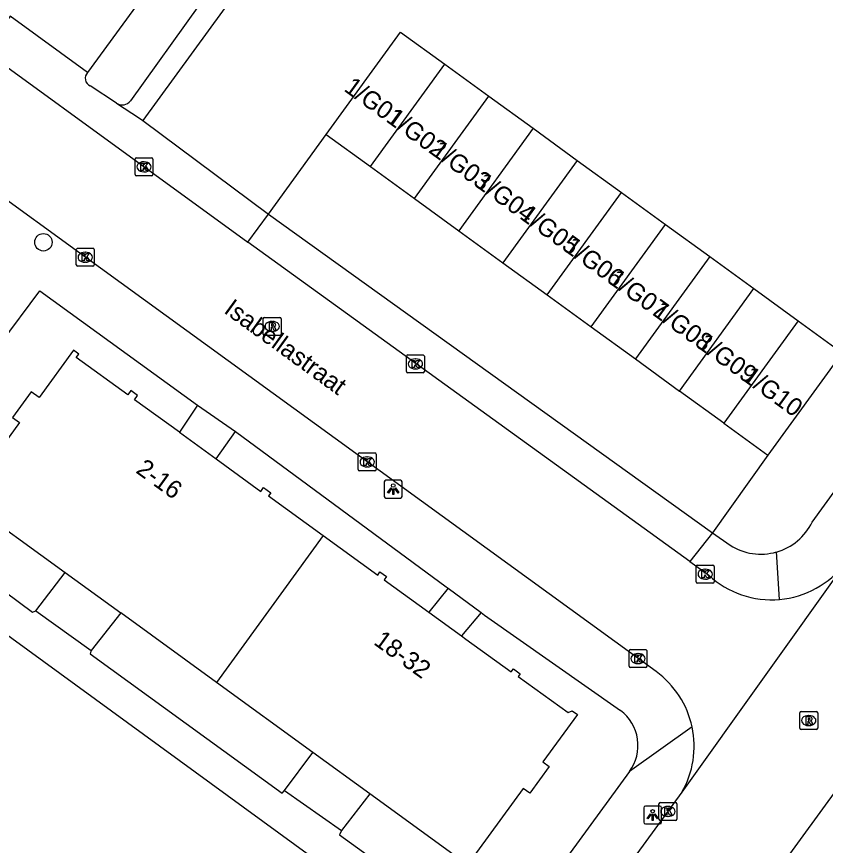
# Model space of a CAD drawing. Extents: x 160107 to 160928, y 382056 to 382918.
# Drawn here: x 160345.01 to 160390.23, y 382406.18 to 382452.51 of the extents above; entities that cross this region are included whole.
import ezdxf

# ---------------------------------------------------------------- set-up
doc = ezdxf.new("R2010")
doc.units = 0
for name, color, linetype in [('IMGEO_Boom', 7, 'Continuous'), ('IMGEO_Kolk', 7, 'Continuous'), ('IMGEO_Lichtpunt', 7, 'Continuous'), ('IMGEO_Openbare_ruimte_label', 7, 'Continuous'), ('IMGEO_Pand', 7, 'Continuous'), ('IMGEO_Pand_nummerreeks', 7, 'Continuous'), ('IMGEO_Parkeervlak_open', 7, 'Continuous'), ('IMGEO_Rijbaan_lokaal_open', 7, 'Continuous'), ('IMGEO_Rioolput', 7, 'Continuous'), ('IMGEO_Voetpad_gesloten', 7, 'Continuous'), ('IMGEO_Voetpad_op_trap', 7, 'Continuous'), ('IMGEO_Voetpad_open', 7, 'Continuous')]:
    doc.layers.add(name, color=color, linetype=linetype)

msp = doc.modelspace()

# ---------------------------------------------------------------- linework, layer by layer
at = {"layer": 'IMGEO_Boom'}
msp.add_circle((160346.516, 382439.892), 0.489, dxfattribs=at)
at = {"layer": 'IMGEO_Kolk'}
for p, q in [((160351.639, 382443.681), (160351.639, 382444.533)), ((160351.714, 382444.607), (160352.566, 382444.607)), ((160352.127, 382444.387), (160352.152, 382444.387)), ((160352.64, 382444.533), (160352.64, 382443.681)), ((160352.566, 382443.607), (160351.714, 382443.607)), ((160352.15, 382443.827), (160352.125, 382443.827)), ((160348.352, 382438.629), (160348.352, 382439.481)), ((160348.427, 382439.555), (160349.279, 382439.555)), ((160348.84, 382439.335), (160348.865, 382439.335)), ((160349.353, 382439.481), (160349.353, 382438.629)), ((160348.863, 382438.775), (160348.838, 382438.775)), ((160349.279, 382438.555), (160348.427, 382438.555)), ((160366.812, 382432.666), (160366.812, 382433.518)), ((160366.887, 382433.592), (160367.739, 382433.592)), ((160367.3, 382433.372), (160367.325, 382433.372)), ((160367.813, 382433.518), (160367.813, 382432.666)), ((160367.323, 382432.812), (160367.298, 382432.812)), ((160367.739, 382432.592), (160366.887, 382432.592)), ((160364.191, 382428.114), (160365.043, 382428.114)), ((160364.116, 382427.188), (160364.116, 382428.04)), ((160364.604, 382427.894), (160364.629, 382427.894)), ((160365.117, 382428.04), (160365.117, 382427.188)), ((160364.627, 382427.334), (160364.602, 382427.334)), ((160365.043, 382427.114), (160364.191, 382427.114)), ((160383.011, 382420.915), (160383.011, 382421.767)), ((160383.086, 382421.841), (160383.938, 382421.841)), ((160383.499, 382421.621), (160383.524, 382421.621)), ((160384.012, 382421.767), (160384.012, 382420.915)), ((160383.938, 382420.841), (160383.086, 382420.841)), ((160383.522, 382421.061), (160383.497, 382421.061)), ((160379.257, 382416.199), (160379.257, 382417.051)), ((160379.332, 382417.125), (160380.184, 382417.125)), ((160380.258, 382417.051), (160380.258, 382416.199)), ((160379.745, 382416.905), (160379.77, 382416.905)), ((160380.184, 382416.125), (160379.332, 382416.125)), ((160379.768, 382416.345), (160379.743, 382416.345)), ((160380.926, 382407.653), (160380.926, 382408.505)), ((160381.001, 382408.579), (160381.853, 382408.579)), ((160381.414, 382408.359), (160381.439, 382408.359)), ((160381.927, 382408.505), (160381.927, 382407.653)), ((160381.437, 382407.799), (160381.412, 382407.799)), ((160381.853, 382407.579), (160381.001, 382407.579))]:
    msp.add_line(p, q, dxfattribs=at)
for points in [[(160351.639, 382443.681), (160351.639, 382444.533)], [(160351.714, 382444.607), (160352.566, 382444.607)], [(160352.64, 382444.533), (160352.64, 382443.681)], [(160351.96, 382444.307), (160352.083, 382444.307), (160352.083, 382444.156), (160352.213, 382444.307), (160352.377, 382444.307), (160352.231, 382444.156), (160352.384, 382443.907), (160352.232, 382443.907), (160352.147, 382444.071), (160352.083, 382444.004), (160352.083, 382443.907), (160351.96, 382443.907), (160351.96, 382444.307)], [(160352.566, 382443.607), (160351.714, 382443.607)], [(160348.352, 382438.629), (160348.352, 382439.481)], [(160348.427, 382439.555), (160349.279, 382439.555)], [(160348.673, 382439.255), (160348.796, 382439.255), (160348.796, 382439.104), (160348.926, 382439.255), (160349.09, 382439.255), (160348.944, 382439.104), (160349.097, 382438.855), (160348.945, 382438.855), (160348.86, 382439.019), (160348.796, 382438.952), (160348.796, 382438.855), (160348.673, 382438.855), (160348.673, 382439.255)], [(160349.353, 382439.481), (160349.353, 382438.629)], [(160349.279, 382438.555), (160348.427, 382438.555)], [(160366.812, 382432.666), (160366.812, 382433.518)], [(160366.887, 382433.592), (160367.739, 382433.592)], [(160367.133, 382433.292), (160367.256, 382433.292), (160367.256, 382433.141), (160367.386, 382433.292), (160367.55, 382433.292), (160367.404, 382433.141), (160367.557, 382432.892), (160367.405, 382432.892), (160367.32, 382433.056), (160367.256, 382432.989), (160367.256, 382432.892), (160367.133, 382432.892), (160367.133, 382433.292)], [(160367.813, 382433.518), (160367.813, 382432.666)], [(160367.739, 382432.592), (160366.887, 382432.592)], [(160364.191, 382428.114), (160365.043, 382428.114)], [(160364.116, 382427.188), (160364.116, 382428.04)], [(160364.437, 382427.814), (160364.56, 382427.814), (160364.56, 382427.663), (160364.69, 382427.814), (160364.854, 382427.814), (160364.708, 382427.663), (160364.861, 382427.414), (160364.709, 382427.414), (160364.624, 382427.578), (160364.56, 382427.511), (160364.56, 382427.414), (160364.437, 382427.414), (160364.437, 382427.814)], [(160365.117, 382428.04), (160365.117, 382427.188)], [(160365.043, 382427.114), (160364.191, 382427.114)], [(160383.011, 382420.915), (160383.011, 382421.767)], [(160383.086, 382421.841), (160383.938, 382421.841)], [(160384.012, 382421.767), (160384.012, 382420.915)], [(160383.332, 382421.541), (160383.455, 382421.541), (160383.455, 382421.39), (160383.585, 382421.541), (160383.749, 382421.541), (160383.603, 382421.39), (160383.756, 382421.141), (160383.604, 382421.141), (160383.519, 382421.305), (160383.455, 382421.238), (160383.455, 382421.141), (160383.332, 382421.141), (160383.332, 382421.541)], [(160383.938, 382420.841), (160383.086, 382420.841)], [(160379.257, 382416.199), (160379.257, 382417.051)], [(160379.332, 382417.125), (160380.184, 382417.125)], [(160380.258, 382417.051), (160380.258, 382416.199)], [(160379.578, 382416.825), (160379.701, 382416.825), (160379.701, 382416.674), (160379.831, 382416.825), (160379.995, 382416.825), (160379.849, 382416.674), (160380.002, 382416.425), (160379.85, 382416.425), (160379.765, 382416.589), (160379.701, 382416.522), (160379.701, 382416.425), (160379.578, 382416.425), (160379.578, 382416.825)], [(160380.184, 382416.125), (160379.332, 382416.125)], [(160380.926, 382407.653), (160380.926, 382408.505)], [(160381.001, 382408.579), (160381.853, 382408.579)], [(160381.247, 382408.279), (160381.37, 382408.279), (160381.37, 382408.128), (160381.5, 382408.279), (160381.664, 382408.279), (160381.518, 382408.128), (160381.671, 382407.879), (160381.519, 382407.879), (160381.434, 382408.043), (160381.37, 382407.976), (160381.37, 382407.879), (160381.247, 382407.879), (160381.247, 382408.279)], [(160381.927, 382408.505), (160381.927, 382407.653)], [(160381.853, 382407.579), (160381.001, 382407.579)]]:
    msp.add_lwpolyline(points, dxfattribs=at)
for centre, start, end in [((160351.716, 382444.531), 91.552, 178.448), ((160351.716, 382444.531), 91.552, 178.448), ((160352.564, 382444.531), 1.552, 88.448), ((160352.564, 382444.531), 1.552, 88.448), ((160351.716, 382443.683), 181.552, 268.448), ((160351.716, 382443.683), 181.552, 268.448), ((160352.564, 382443.683), 271.552, 358.448), ((160352.564, 382443.683), 271.552, 358.448), ((160348.429, 382439.479), 91.552, 178.448), ((160348.429, 382439.479), 91.552, 178.448), ((160349.277, 382439.479), 1.552, 88.448), ((160349.277, 382439.479), 1.552, 88.448), ((160348.429, 382438.631), 181.552, 268.448), ((160348.429, 382438.631), 181.552, 268.448), ((160349.277, 382438.631), 271.552, 358.448), ((160349.277, 382438.631), 271.552, 358.448), ((160366.889, 382433.516), 91.552, 178.448), ((160366.889, 382433.516), 91.552, 178.448), ((160367.737, 382433.516), 1.552, 88.448), ((160367.737, 382433.516), 1.552, 88.448), ((160366.889, 382432.668), 181.552, 268.448), ((160366.889, 382432.668), 181.552, 268.448), ((160367.737, 382432.668), 271.552, 358.448), ((160367.737, 382432.668), 271.552, 358.448), ((160364.193, 382428.038), 91.552, 178.448), ((160364.193, 382428.038), 91.552, 178.448), ((160365.041, 382428.038), 1.552, 88.448), ((160365.041, 382428.038), 1.552, 88.448), ((160364.193, 382427.19), 181.552, 268.448), ((160364.193, 382427.19), 181.552, 268.448), ((160365.041, 382427.19), 271.552, 358.448), ((160365.041, 382427.19), 271.552, 358.448), ((160383.088, 382421.765), 91.552, 178.448), ((160383.088, 382421.765), 91.552, 178.448), ((160383.936, 382421.765), 1.552, 88.448), ((160383.936, 382421.765), 1.552, 88.448), ((160383.088, 382420.917), 181.552, 268.448), ((160383.088, 382420.917), 181.552, 268.448), ((160383.936, 382420.917), 271.552, 358.448), ((160383.936, 382420.917), 271.552, 358.448), ((160379.334, 382417.049), 91.552, 178.448), ((160379.334, 382417.049), 91.552, 178.448), ((160380.182, 382417.049), 1.552, 88.448), ((160380.182, 382417.049), 1.552, 88.448), ((160379.334, 382416.201), 181.552, 268.448), ((160379.334, 382416.201), 181.552, 268.448), ((160380.182, 382416.201), 271.552, 358.448), ((160380.182, 382416.201), 271.552, 358.448), ((160381.003, 382408.503), 91.552, 178.448), ((160381.003, 382408.503), 91.552, 178.448), ((160381.851, 382408.503), 1.552, 88.448), ((160381.851, 382408.503), 1.552, 88.448), ((160381.003, 382407.655), 181.552, 268.448), ((160381.003, 382407.655), 181.552, 268.448), ((160381.851, 382407.655), 271.552, 358.448), ((160381.851, 382407.655), 271.552, 358.448)]:
    msp.add_arc(centre, 0.0765, start, end, dxfattribs=at)
for centre, major_axis, ratio, start_param, end_param in [((160352.126, 382444.107), (-0.387, 0.002), 0.722429, 4.712389, 7.853982), ((160352.151, 382444.107), (-0.39, 0.002), 0.717154, 1.570796, 4.712389), ((160348.839, 382439.055), (-0.387, 0.002), 0.722429, 4.712389, 7.853982), ((160348.864, 382439.055), (-0.39, 0.002), 0.717154, 1.570796, 4.712389), ((160367.299, 382433.092), (-0.387, 0.002), 0.722429, 4.712389, 7.853982), ((160367.324, 382433.092), (-0.39, 0.002), 0.717154, 1.570796, 4.712389), ((160364.603, 382427.614), (-0.387, 0.002), 0.722429, 4.712389, 7.853982), ((160364.628, 382427.614), (-0.39, 0.002), 0.717154, 1.570796, 4.712389), ((160383.498, 382421.341), (-0.387, 0.002), 0.722429, 4.712389, 7.853982), ((160383.523, 382421.341), (-0.39, 0.002), 0.717154, 1.570796, 4.712389), ((160379.744, 382416.625), (-0.387, 0.002), 0.722429, 4.712389, 7.853982), ((160379.769, 382416.625), (-0.39, 0.002), 0.717154, 1.570796, 4.712389), ((160381.413, 382408.079), (-0.387, 0.002), 0.722429, 4.712389, 7.853982), ((160381.438, 382408.079), (-0.39, 0.002), 0.717154, 1.570796, 4.712389)]:
    msp.add_ellipse(centre, major_axis=major_axis, ratio=ratio, start_param=start_param, end_param=end_param, dxfattribs=at)
at = {"layer": 'IMGEO_Lichtpunt'}
for p, q in [((160365.573, 382426.497), (160365.573, 382425.69)), ((160365.573, 382426.497), (160365.573, 382425.69)), ((160366.475, 382426.592), (160365.667, 382426.592)), ((160366.475, 382426.592), (160365.667, 382426.592)), ((160366.569, 382425.69), (160366.569, 382426.497)), ((160366.569, 382425.69), (160366.569, 382426.497)), ((160365.667, 382425.596), (160366.475, 382425.596)), ((160365.667, 382425.596), (160366.475, 382425.596)), ((160380.073, 382408.289), (160380.073, 382407.482)), ((160380.073, 382408.289), (160380.073, 382407.482)), ((160380.975, 382408.384), (160380.167, 382408.384)), ((160380.975, 382408.384), (160380.167, 382408.384)), ((160381.069, 382407.482), (160381.069, 382408.289)), ((160381.069, 382407.482), (160381.069, 382408.289)), ((160380.167, 382407.388), (160380.975, 382407.388)), ((160380.167, 382407.388), (160380.975, 382407.388))]:
    msp.add_line(p, q, dxfattribs=at)
for points in [[(160365.947, 382426.161), (160365.986, 382426.133), (160365.798, 382425.871), (160365.76, 382425.898), (160365.947, 382426.161)], [(160366.049, 382426.113), (160366.096, 382426.113), (160366.096, 382425.791), (160366.049, 382425.791), (160366.049, 382426.113)], [(160366.159, 382426.133), (160366.197, 382426.16), (160366.384, 382425.898), (160366.345, 382425.87), (160366.159, 382426.133)], [(160380.447, 382407.953), (160380.486, 382407.925), (160380.298, 382407.663), (160380.26, 382407.69), (160380.447, 382407.953)], [(160380.549, 382407.905), (160380.596, 382407.905), (160380.596, 382407.583), (160380.549, 382407.583), (160380.549, 382407.905)], [(160380.659, 382407.925), (160380.697, 382407.952), (160380.884, 382407.69), (160380.845, 382407.662), (160380.659, 382407.925)]]:
    msp.add_lwpolyline(points, dxfattribs=at)
for centre in [(160366.072, 382426.295), (160380.572, 382408.087)]:
    msp.add_circle(centre, 0.0994, dxfattribs=at)
for centre, start, end in [((160365.667, 382426.497), 90, 180), ((160365.667, 382426.497), 90, 180), ((160366.475, 382426.497), 0, 90), ((160366.475, 382426.497), 0, 90), ((160365.667, 382425.69), 180, 270), ((160365.667, 382425.69), 180, 270), ((160366.475, 382425.69), 270, 0), ((160366.475, 382425.69), 270, 360), ((160380.167, 382408.289), 90, 180), ((160380.167, 382408.289), 90, 180), ((160380.975, 382408.289), 0, 90), ((160380.975, 382408.289), 0, 90), ((160380.167, 382407.482), 180, 270), ((160380.167, 382407.482), 180, 270), ((160380.975, 382407.482), 270, 0), ((160380.975, 382407.482), 270, 360)]:
    msp.add_arc(centre, 0.0946, start, end, dxfattribs=at)
at = {"layer": 'IMGEO_Pand'}
for points in [[(160348.989, 382449.382), (160344.664, 382452.524), (160344.401, 382452.162), (160342.917, 382453.24), (160343.15, 382453.56), (160340.556, 382455.444)], [(160352.927, 382454.801), (160348.989, 382449.382)], [(160362.329, 382445.915), (160366.484, 382451.639), (160368.953, 382449.846)], [(160364.798, 382444.123), (160368.953, 382449.846)], [(160368.953, 382449.846), (160371.422, 382448.054)], [(160367.267, 382442.33), (160371.422, 382448.054)], [(160371.422, 382448.054), (160373.891, 382446.261)], [(160373.891, 382446.261), (160369.736, 382440.538)], [(160373.891, 382446.261), (160376.36, 382444.469)], [(160362.329, 382445.915), (160364.798, 382444.123)], [(160376.36, 382444.469), (160372.205, 382438.745)], [(160376.36, 382444.469), (160378.829, 382442.676)], [(160364.798, 382444.123), (160367.267, 382442.33)], [(160374.674, 382436.953), (160378.829, 382442.676)], [(160378.829, 382442.676), (160381.297, 382440.884)], [(160367.267, 382442.33), (160369.736, 382440.538)], [(160377.142, 382435.161), (160381.297, 382440.884)], [(160381.297, 382440.884), (160383.766, 382439.091)], [(160369.736, 382440.538), (160372.205, 382438.745)], [(160383.766, 382439.091), (160379.611, 382433.368)], [(160383.766, 382439.091), (160386.235, 382437.299)], [(160372.205, 382438.745), (160374.674, 382436.953)], [(160374.674, 382436.953), (160377.142, 382435.161)], [(160382.08, 382431.576), (160386.235, 382437.299)], [(160386.235, 382437.299), (160388.704, 382435.507)], [(160388.704, 382435.507), (160384.549, 382429.783)], [(160388.704, 382435.507), (160391.173, 382433.714), (160387.018, 382427.991)], [(160377.142, 382435.161), (160379.611, 382433.368)], [(160354.123, 382429.27), (160351.609, 382431.094), (160351.776, 382431.324), (160351.397, 382431.599), (160351.228, 382431.367), (160348.355, 382433.452), (160348.496, 382433.646), (160348.196, 382433.864), (160346.277, 382431.219), (160345.836, 382431.539), (160344.791, 382430.1), (160345.171, 382429.825), (160342.062, 382425.541), (160347.73, 382421.428)], [(160379.611, 382433.368), (160382.08, 382431.576)], [(160384.549, 382429.783), (160382.08, 382431.576)], [(160384.549, 382429.783), (160387.018, 382427.991)], [(160354.123, 382429.27), (160356.176, 382427.78)], [(160356.176, 382427.78), (160358.668, 382425.971), (160358.82, 382426.179), (160359.222, 382425.887), (160359.103, 382425.723), (160362.154, 382423.509)], [(160362.154, 382423.509), (160356.188, 382415.289)], [(160362.154, 382423.509), (160365.205, 382421.294), (160365.329, 382421.464), (160365.688, 382421.204), (160365.562, 382421.031), (160368.056, 382419.221)], [(160347.73, 382421.428), (160350.837, 382419.173)], [(160356.188, 382415.289), (160350.837, 382419.173)], [(160368.056, 382419.221), (160369.885, 382417.893)], [(160369.885, 382417.893), (160370.139, 382417.709), (160372.658, 382415.881), (160372.787, 382416.059), (160373.175, 382415.778), (160373.062, 382415.622), (160375.845, 382413.602), (160376.08, 382413.707), (160376.369, 382413.498), (160374.443, 382410.845), (160374.79, 382410.593), (160373.701, 382409.093), (160373.327, 382409.365), (160370.23, 382405.098), (160364.767, 382409.063)], [(160361.58, 382411.376), (160356.188, 382415.289)], [(160364.767, 382409.063), (160361.58, 382411.376)]]:
    msp.add_lwpolyline(points, dxfattribs=at)
at = {"layer": 'IMGEO_Parkeervlak_open'}
for points in [[(160359.103, 382441.461), (160362.329, 382445.915)], [(160387.018, 382427.991), (160383.929, 382423.658)]]:
    msp.add_lwpolyline(points, dxfattribs=at)
at = {"layer": 'IMGEO_Rijbaan_lokaal_open'}
for points in [[(160336.283, 382455.687), (160337.07, 382455.076), (160357.942, 382439.895)], [(160380.766, 382415.895), (160348.555, 382439.273), (160333.601, 382450.126)], [(160382.647, 382422.051), (160357.942, 382439.895)], [(160401.997, 382424.596), (160401.868, 382424.419), (160350.937, 382354.514)], [(160391.333, 382421.95), (160391.318, 382421.917), (160382.213, 382409.153)], [(160382.647, 382422.051), (160383.708, 382421.284)], [(160382.213, 382409.153), (160345.726, 382359.174)]]:
    msp.add_lwpolyline(points, dxfattribs=at)
for centre, radius, start, end in [((160387.219, 382425.084), 5.172, 274.9776, 322.698), ((160387.217, 382425.087), 5.175, 227.303, 274.9957), ((160377.726, 382411.715), 5.169, 12.1278, 53.9694), ((160377.728, 382411.717), 5.166, 330.2476, 12.1137)]:
    msp.add_arc(centre, radius, start, end, dxfattribs=at)
at = {"layer": 'IMGEO_Rioolput'}
for p, q in [((160358.805, 382434.76), (160358.805, 382435.612)), ((160358.88, 382435.686), (160359.732, 382435.686)), ((160359.806, 382435.612), (160359.806, 382434.76)), ((160359.293, 382435.466), (160359.318, 382435.466)), ((160359.732, 382434.686), (160358.88, 382434.686)), ((160359.316, 382434.906), (160359.291, 382434.906)), ((160388.799, 382412.736), (160388.799, 382413.588)), ((160388.874, 382413.662), (160389.726, 382413.662)), ((160389.287, 382413.442), (160389.312, 382413.442)), ((160389.8, 382413.588), (160389.8, 382412.736)), ((160389.31, 382412.882), (160389.285, 382412.882)), ((160389.726, 382412.662), (160388.874, 382412.662))]:
    msp.add_line(p, q, dxfattribs=at)
for points in [[(160358.805, 382434.76), (160358.805, 382435.612)], [(160358.88, 382435.686), (160359.732, 382435.686)], [(160359.806, 382435.612), (160359.806, 382434.76)], [(160359.394, 382435.384), (160359.142, 382435.386), (160359.142, 382434.986)], [(160359.142, 382434.986), (160359.266, 382434.986), (160359.266, 382435.148), (160359.277, 382435.148)], [(160359.32, 382435.305), (160359.266, 382435.305), (160359.266, 382435.224)], [(160359.266, 382435.224), (160359.318, 382435.224)], [(160359.324, 382435.119), (160359.395, 382434.986), (160359.535, 382434.986), (160359.47, 382435.112)], [(160359.732, 382434.686), (160358.88, 382434.686)], [(160388.799, 382412.736), (160388.799, 382413.588)], [(160388.874, 382413.662), (160389.726, 382413.662)], [(160389.388, 382413.36), (160389.136, 382413.362), (160389.136, 382412.962)], [(160389.314, 382413.281), (160389.26, 382413.281), (160389.26, 382413.2)], [(160389.8, 382413.588), (160389.8, 382412.736)], [(160389.136, 382412.962), (160389.26, 382412.962), (160389.26, 382413.124), (160389.271, 382413.124)], [(160389.26, 382413.2), (160389.312, 382413.2)], [(160389.318, 382413.095), (160389.389, 382412.962), (160389.529, 382412.962), (160389.464, 382413.088)], [(160389.726, 382412.662), (160388.874, 382412.662)]]:
    msp.add_lwpolyline(points, dxfattribs=at)
for centre, radius, start, end in [((160358.882, 382435.61), 0.0765, 91.552, 178.448), ((160358.882, 382435.61), 0.0765, 91.552, 178.448), ((160359.73, 382435.61), 0.0765, 1.552, 88.448), ((160359.73, 382435.61), 0.0765, 1.552, 88.448), ((160359.276, 382435.095), 0.0533, 26.0293, 88.6989), ((160359.302, 382435.413), 0.19, 274.7715, 282.9687), ((160359.326, 382435.209), 0.0964, 77.0061, 93.1865), ((160359.34, 382435.266), 0.0378, 276.6634, 79.6772), ((160359.393, 382435.274), 0.109, 350.3612, 89.416), ((160359.391, 382435.274), 0.112, 277.5842, 350.9817), ((160359.375, 382435.059), 0.108, 29.5134, 73.7905), ((160358.882, 382434.762), 0.0765, 181.552, 268.448), ((160358.882, 382434.762), 0.0765, 181.552, 268.448), ((160359.73, 382434.762), 0.0765, 271.552, 358.448), ((160359.73, 382434.762), 0.0765, 271.552, 358.448), ((160388.876, 382413.586), 0.0765, 91.552, 178.448), ((160388.876, 382413.586), 0.0765, 91.552, 178.448), ((160389.32, 382413.185), 0.0964, 77.0061, 93.1865), ((160389.334, 382413.242), 0.0378, 276.6634, 79.6772), ((160389.387, 382413.25), 0.109, 350.3612, 89.416), ((160389.724, 382413.586), 0.0765, 1.552, 88.448), ((160389.724, 382413.586), 0.0765, 1.552, 88.448), ((160389.27, 382413.071), 0.0533, 26.0293, 88.6989), ((160389.296, 382413.389), 0.19, 274.7715, 282.9687), ((160389.385, 382413.25), 0.112, 277.5842, 350.9817), ((160389.369, 382413.035), 0.108, 29.5134, 73.7905), ((160388.876, 382412.738), 0.0765, 181.552, 268.448), ((160388.876, 382412.738), 0.0765, 181.552, 268.448), ((160389.724, 382412.738), 0.0765, 271.552, 358.448), ((160389.724, 382412.738), 0.0765, 271.552, 358.448)]:
    msp.add_arc(centre, radius, start, end, dxfattribs=at)
for centre, major_axis, ratio, start_param, end_param in [((160359.292, 382435.186), (-0.387, 0.002), 0.722429, 4.712389, 7.853982), ((160359.317, 382435.186), (-0.39, 0.002), 0.717154, 1.570796, 4.712389), ((160389.286, 382413.162), (-0.387, 0.002), 0.722429, 4.712389, 7.853982), ((160389.311, 382413.162), (-0.39, 0.002), 0.717154, 1.570796, 4.712389)]:
    msp.add_ellipse(centre, major_axis=major_axis, ratio=ratio, start_param=start_param, end_param=end_param, dxfattribs=at)
at = {"layer": 'IMGEO_Voetpad_gesloten'}
for points in [[(160355.13, 382430.78), (160354.123, 382429.27)], [(160355.13, 382430.78), (160357.258, 382429.311)], [(160356.176, 382427.78), (160357.258, 382429.311)], [(160369.144, 382420.555), (160368.056, 382419.221)], [(160369.144, 382420.555), (160370.988, 382419.193)], [(160370.988, 382419.193), (160369.885, 382417.893)]]:
    msp.add_lwpolyline(points, dxfattribs=at)
at = {"layer": 'IMGEO_Voetpad_op_trap'}
for points in [[(160346.099, 382419.291), (160347.73, 382421.428)], [(160350.837, 382419.173), (160349.192, 382417.077)], [(160359.997, 382409.254), (160361.58, 382411.376)], [(160364.767, 382409.063), (160363.18, 382407.011)]]:
    msp.add_lwpolyline(points, dxfattribs=at)
at = {"layer": 'IMGEO_Voetpad_open'}
for points in [[(160422.2, 382470.206), (160417.015, 382473.964), (160416.838, 382473.717), (160390.944, 382492.372), (160384.801, 382491.609), (160352.064, 382446.689)], [(160389.495, 382424.254), (160422.478, 382469.715)], [(160355.108, 382453.371), (160355.21, 382453.121), (160351.386, 382447.802)], [(160350.607, 382447.664), (160349.132, 382448.638)], [(160350.607, 382447.664), (160351.883, 382446.823), (160352.064, 382446.689)], [(160352.064, 382446.689), (160359.103, 382441.461)], [(160357.942, 382439.895), (160359.103, 382441.461)], [(160359.103, 382441.461), (160383.929, 382423.658)], [(160344.086, 382434.199), (160346.323, 382437.183), (160355.13, 382430.78)], [(160344.086, 382434.199), (160337.524, 382425.446), (160345.91, 382419.22), (160346.099, 382419.291)], [(160357.258, 382429.311), (160369.038, 382420.633), (160369.144, 382420.555)], [(160370.829, 382398.747), (160336.272, 382423.908), (160301.535, 382376.068)], [(160383.929, 382423.658), (160382.647, 382422.051)], [(160383.929, 382423.658), (160384.908, 382422.956)], [(160387.668, 382419.932), (160387.491, 382422.581)], [(160346.099, 382419.291), (160349.192, 382417.077)], [(160370.988, 382419.193), (160371.177, 382419.054), (160378.769, 382413.727)], [(160349.192, 382417.077), (160349.132, 382416.887), (160359.858, 382409.104), (160359.997, 382409.254)], [(160382.779, 382412.801), (160379.276, 382410.307)], [(160379.276, 382410.307), (160371.989, 382400.333)], [(160359.997, 382409.254), (160363.18, 382407.011)], [(160363.18, 382407.011), (160363.061, 382406.781), (160371.989, 382400.333)]]:
    msp.add_lwpolyline(points, dxfattribs=at)
for centre, radius, start, end in [((160349.305, 382449.057), 0.453, 134.2119, 247.5478), ((160350.923, 382448.148), 0.578, 236.8906, 323.2009), ((160386.618, 382425.663), 3.204, 285.8122, 333.9001), ((160386.619, 382425.659), 3.199, 237.6621, 285.817), ((160377.313, 382411.764), 2.444, 323.4216, 53.4433)]:
    msp.add_arc(centre, radius, start, end, dxfattribs=at)

# ---------------------------------------------------------------- texts
at = {"layer": 'IMGEO_Openbare_ruimte_label'}
msp.add_text('Isabellastraat', height=1, rotation=324.0358, dxfattribs=at).set_placement((160356.549, 382435.985))
at = {"layer": 'IMGEO_Pand_nummerreeks'}
for s, rotation, p in [('1/G01', 324.033, (160363.263, 382448.388)), ('1/G02', 324.033, (160365.645, 382446.659)), ('1/G03', 324.033, (160368.127, 382444.859)), ('1/G04', 324.033, (160370.603, 382443.061)), ('1/G05', 324.033, (160373.08, 382441.264)), ('1/G06', 324.033, (160375.556, 382439.467)), ('1/G07', 324.033, (160378.033, 382437.67)), ('1/G08', 324.033, (160380.512, 382435.871)), ('1/G09', 324.033, (160382.983, 382434.078)), ('1/G10', 324.033, (160385.539, 382432.223)), ('2-16', 324.2245, (160351.631, 382427.048)), ('18-32', 324.1099, (160364.922, 382417.458))]:
    msp.add_text(s, height=1, rotation=rotation, dxfattribs=at).set_placement(p)

doc.saveas('drawing.dxf')
